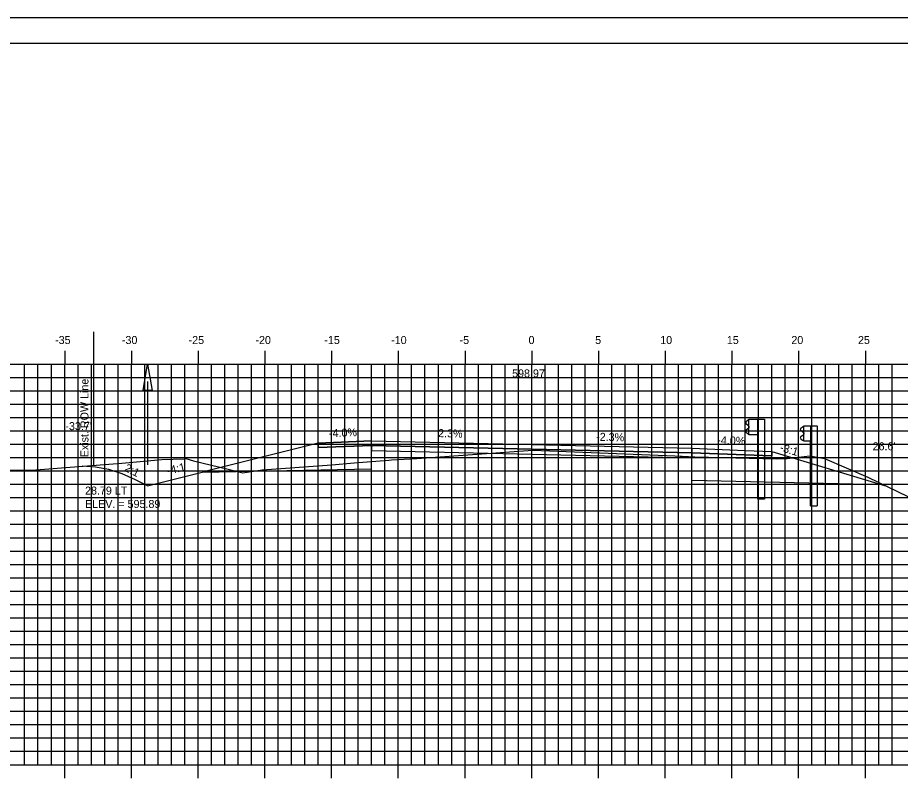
# Model space of a CAD drawing. Extents: x 1073864 to 1074034, y 779716 to 779826.
# Drawn here: x 1073908.9 to 1073975.1, y 779768.5 to 779825.6 of the extents above; entities that cross this region are included whole.
import ezdxf

# ---------------------------------------------------------------- set-up
doc = ezdxf.new("R2010")
doc.units = 0
for name, color, linetype in [('ANNOTATION', 7, 'Continuous'), ('BORDER', 7, 'Continuous'), ('D_Drainage_Ditch_Line', 7, 'Continuous'), ('D_Guardrail_Beam_Rt', 7, 'Continuous'), ('D_Roadway_Centerline', 7, 'Continuous'), ('D_Roadway_Centerline_Text', 7, 'Continuous'), ('D_Roadway_Edge_Pavement', 7, 'Continuous'), ('D_Roadway_Edge_Shoulder', 7, 'Continuous'), ('D_Roadway_Pavement', 7, 'Continuous'), ('D_Roadway_SlopeLines', 7, 'Continuous'), ('D_Roadway_SubGrade', 7, 'Continuous'), ('D_Text_Standard', 7, 'Continuous'), ('E_ROW_Line', 7, 'Continuous'), ('H_V ANNOTATION', 7, 'Continuous'), ('M_Guardrail', 7, 'Continuous'), ('MAJOR', 7, 'Continuous'), ('MINOR', 7, 'Continuous'), ('PLOT BOUNDARY', 7, 'Continuous'), ('S_Guardrail_Beam', 7, 'Continuous'), ('S_Roadway_Centerline', 7, 'Continuous')]:
    doc.layers.add(name, color=color, linetype=linetype)

msp = doc.modelspace()

# ---------------------------------------------------------------- linework, layer by layer
at = {"layer": 'BORDER'}
msp.add_lwpolyline([(1073872.472, 779718.706), (1074032.472, 779718.706), (1074032.472, 779823.706), (1073872.472, 779823.706)], close=True, dxfattribs=at)
at = {"layer": 'D_Drainage_Ditch_Line'}
msp.add_line((1073918.687, 779798.393), (1073918.687, 779792.15), dxfattribs=at)
msp.add_lwpolyline([(1073919.015, 779797.737), (1073918.359, 779797.737), (1073918.687, 779799.706)], close=True, dxfattribs=at)
at = {"layer": 'D_Guardrail_Beam_Rt'}
msp.add_lwpolyline([(1073963.751, 779795.512), (1073963.669, 779795.498), (1073963.652, 779795.491), (1073963.509, 779795.39), (1073963.509, 779795.247), (1073963.704, 779795.111), (1073963.738, 779795.046), (1073963.738, 779794.955), (1073963.704, 779794.89), (1073963.509, 779794.754), (1073963.509, 779794.611), (1073963.652, 779794.51), (1073963.669, 779794.504), (1073963.751, 779794.489)], dxfattribs=at)
for points in [[(1073963.751, 779795.591), (1073964.417, 779795.591), (1073964.417, 779794.41), (1073963.751, 779794.41)], [(1073964.417, 779795.591), (1073964.91, 779795.591), (1073964.91, 779789.587), (1073964.417, 779789.587)]]:
    msp.add_lwpolyline(points, close=True, dxfattribs=at)
at = {"layer": 'D_Roadway_Centerline'}
for points in [[(1073931.472, 779793.792), (1073935.472, 779793.952), (1073947.472, 779793.676), (1073959.472, 779793.4), (1073963.472, 779793.24), (1073965.472, 779793.16)], [(1073918.687, 779790.596), (1073922.762, 779791.614)], [(1073973.738, 779790.655), (1073974.082, 779790.551)]]:
    msp.add_lwpolyline(points, dxfattribs=at)
at = {"layer": 'D_Roadway_Edge_Pavement'}
msp.add_lwpolyline([(1073935.472, 779793.619), (1073935.472, 779793.952), (1073947.472, 779793.676), (1073959.472, 779793.4), (1073959.472, 779793.067), (1073947.472, 779793.343)], close=True, dxfattribs=at)
at = {"layer": 'D_Roadway_Edge_Shoulder'}
msp.add_lwpolyline([(1073935.472, 779793.952), (1073931.472, 779793.792), (1073931.472, 779793.459), (1073935.472, 779793.619)], close=True, dxfattribs=at)
msp.add_lwpolyline([(1073959.472, 779793.4), (1073963.472, 779793.24), (1073965.472, 779793.16), (1073965.472, 779792.827), (1073959.472, 779793.067), (1073959.472, 779793.4)], dxfattribs=at)
at = {"layer": 'D_Roadway_Pavement'}
msp.add_lwpolyline([(1073935.472, 779793.202), (1073935.472, 779793.619), (1073947.472, 779793.343), (1073959.472, 779793.067), (1073959.472, 779792.65), (1073947.472, 779792.926)], close=True, dxfattribs=at)
msp.add_lwpolyline([(1073935.472, 779793.619), (1073935.472, 779793.202)], dxfattribs=at)
at = {"layer": 'D_Roadway_SlopeLines'}
for points in [[(1073935.472, 779793.952), (1073931.472, 779793.792)], [(1073918.687, 779790.596), (1073917.78, 779791.049), (1073916.78, 779791.488), (1073915.78, 779791.802), (1073914.78, 779791.993), (1073913.78, 779792.059)]]:
    msp.add_lwpolyline(points, dxfattribs=at)
at = {"layer": 'D_Roadway_SubGrade'}
for points in [[(1073935.472, 779793.619), (1073931.472, 779793.459), (1073931.472, 779793.792), (1073922.762, 779791.614), (1073935.472, 779791.869), (1073935.472, 779793.619)], [(1073959.472, 779790.983), (1073959.472, 779791.567), (1073959.472, 779793.067), (1073959.472, 779793.067), (1073965.472, 779792.827), (1073965.472, 779793.16), (1073973.738, 779790.655)]]:
    msp.add_lwpolyline(points, close=True, dxfattribs=at)
at = {"layer": 'E_ROW_Line'}
msp.add_line((1073914.653, 779792.126), (1073914.653, 779802.126), dxfattribs=at)
msp.add_line((1073914.653, 779792.126), (1073914.653, 779802.126), dxfattribs=at)
at = {"layer": 'M_Guardrail'}
for p, q in [((1073968.359, 779795.087), (1073968.85, 779795.087)), ((1073968.85, 779795.087), (1073968.85, 779789.087)), ((1073968.359, 779789.087), (1073968.359, 779793.921)), ((1073968.359, 779789.087), (1073968.85, 779789.087))]:
    msp.add_line(p, q, dxfattribs=at)
at = {"layer": 'MAJOR'}
for p, q in [((1073912.472, 779800.708), (1073912.472, 779799.706)), ((1073917.472, 779800.708), (1073917.472, 779799.706)), ((1073922.472, 779800.708), (1073922.472, 779799.706)), ((1073927.472, 779800.708), (1073927.472, 779799.706)), ((1073932.472, 779800.708), (1073932.472, 779799.706)), ((1073937.472, 779800.708), (1073937.472, 779799.706)), ((1073942.472, 779800.708), (1073942.472, 779799.706)), ((1073947.472, 779800.708), (1073947.472, 779799.706)), ((1073952.472, 779800.708), (1073952.472, 779799.706)), ((1073957.472, 779800.708), (1073957.472, 779799.706)), ((1073962.472, 779800.708), (1073962.472, 779799.706)), ((1073967.472, 779800.708), (1073967.472, 779799.706)), ((1073972.472, 779800.708), (1073972.472, 779799.706)), ((1073877.472, 779799.706), (1074017.472, 779799.706)), ((1073877.472, 779799.706), (1074017.472, 779799.706)), ((1073912.472, 779769.706), (1073912.472, 779799.706)), ((1073917.472, 779769.706), (1073917.472, 779799.706)), ((1073922.472, 779769.706), (1073922.472, 779799.706)), ((1073927.472, 779769.706), (1073927.472, 779799.706)), ((1073932.472, 779769.706), (1073932.472, 779799.706)), ((1073937.472, 779769.706), (1073937.472, 779799.706)), ((1073942.472, 779769.706), (1073942.472, 779799.706)), ((1073947.472, 779769.706), (1073947.472, 779799.706)), ((1073952.472, 779769.706), (1073952.472, 779799.706)), ((1073957.472, 779769.706), (1073957.472, 779799.706)), ((1073962.472, 779769.706), (1073962.472, 779799.706)), ((1073967.472, 779769.706), (1073967.472, 779799.706)), ((1073972.472, 779769.706), (1073972.472, 779799.706)), ((1073877.472, 779794.706), (1074017.472, 779794.706)), ((1073877.472, 779789.706), (1074017.472, 779789.706)), ((1073877.472, 779784.706), (1074017.472, 779784.706)), ((1073877.472, 779779.706), (1074017.472, 779779.706)), ((1073877.472, 779774.706), (1074017.472, 779774.706)), ((1073877.472, 779769.706), (1074017.472, 779769.706)), ((1073877.472, 779769.706), (1074017.472, 779769.706)), ((1073912.472, 779768.704), (1073912.472, 779769.706)), ((1073917.472, 779768.704), (1073917.472, 779769.706)), ((1073922.472, 779768.704), (1073922.472, 779769.706)), ((1073927.472, 779768.704), (1073927.472, 779769.706)), ((1073932.472, 779768.704), (1073932.472, 779769.706)), ((1073937.472, 779768.704), (1073937.472, 779769.706)), ((1073942.472, 779768.704), (1073942.472, 779769.706)), ((1073947.472, 779768.704), (1073947.472, 779769.706)), ((1073952.472, 779768.704), (1073952.472, 779769.706)), ((1073957.472, 779768.704), (1073957.472, 779769.706)), ((1073962.472, 779768.704), (1073962.472, 779769.706)), ((1073967.472, 779768.704), (1073967.472, 779769.706)), ((1073972.472, 779768.704), (1073972.472, 779769.706))]:
    msp.add_line(p, q, dxfattribs=at)
at = {"layer": 'MINOR'}
for p, q in [((1073909.472, 779769.706), (1073909.472, 779799.706)), ((1073910.472, 779769.706), (1073910.472, 779799.706)), ((1073911.472, 779769.706), (1073911.472, 779799.706)), ((1073913.472, 779769.706), (1073913.472, 779799.706)), ((1073914.472, 779769.706), (1073914.472, 779799.706)), ((1073915.472, 779769.706), (1073915.472, 779799.706)), ((1073916.472, 779769.706), (1073916.472, 779799.706)), ((1073918.472, 779769.706), (1073918.472, 779799.706)), ((1073919.472, 779769.706), (1073919.472, 779799.706)), ((1073920.472, 779769.706), (1073920.472, 779799.706)), ((1073921.472, 779769.706), (1073921.472, 779799.706)), ((1073923.472, 779769.706), (1073923.472, 779799.706)), ((1073924.472, 779769.706), (1073924.472, 779799.706)), ((1073925.472, 779769.706), (1073925.472, 779799.706)), ((1073926.472, 779769.706), (1073926.472, 779799.706)), ((1073928.472, 779769.706), (1073928.472, 779799.706)), ((1073929.472, 779769.706), (1073929.472, 779799.706)), ((1073930.472, 779769.706), (1073930.472, 779799.706)), ((1073931.472, 779769.706), (1073931.472, 779799.706)), ((1073933.472, 779769.706), (1073933.472, 779799.706)), ((1073934.472, 779769.706), (1073934.472, 779799.706)), ((1073935.472, 779769.706), (1073935.472, 779799.706)), ((1073936.472, 779769.706), (1073936.472, 779799.706)), ((1073938.472, 779769.706), (1073938.472, 779799.706)), ((1073939.472, 779769.706), (1073939.472, 779799.706)), ((1073940.472, 779769.706), (1073940.472, 779799.706)), ((1073941.472, 779769.706), (1073941.472, 779799.706)), ((1073943.472, 779769.706), (1073943.472, 779799.706)), ((1073944.472, 779769.706), (1073944.472, 779799.706)), ((1073945.472, 779769.706), (1073945.472, 779799.706)), ((1073946.472, 779769.706), (1073946.472, 779799.706)), ((1073948.472, 779769.706), (1073948.472, 779799.706)), ((1073949.472, 779769.706), (1073949.472, 779799.706)), ((1073950.472, 779769.706), (1073950.472, 779799.706)), ((1073951.472, 779769.706), (1073951.472, 779799.706)), ((1073953.472, 779769.706), (1073953.472, 779799.706)), ((1073954.472, 779769.706), (1073954.472, 779799.706)), ((1073955.472, 779769.706), (1073955.472, 779799.706)), ((1073956.472, 779769.706), (1073956.472, 779799.706)), ((1073958.472, 779769.706), (1073958.472, 779799.706)), ((1073959.472, 779769.706), (1073959.472, 779799.706)), ((1073960.472, 779769.706), (1073960.472, 779799.706)), ((1073961.472, 779769.706), (1073961.472, 779799.706)), ((1073963.472, 779769.706), (1073963.472, 779799.706)), ((1073964.472, 779769.706), (1073964.472, 779799.706)), ((1073965.472, 779769.706), (1073965.472, 779799.706)), ((1073966.472, 779769.706), (1073966.472, 779799.706)), ((1073968.472, 779769.706), (1073968.472, 779799.706)), ((1073969.472, 779769.706), (1073969.472, 779799.706)), ((1073970.472, 779769.706), (1073970.472, 779799.706)), ((1073971.472, 779769.706), (1073971.472, 779799.706)), ((1073973.472, 779769.706), (1073973.472, 779799.706)), ((1073974.472, 779769.706), (1073974.472, 779799.706)), ((1073877.472, 779798.706), (1074017.472, 779798.706)), ((1073877.472, 779797.706), (1074017.472, 779797.706)), ((1073877.472, 779796.706), (1074017.472, 779796.706)), ((1073877.472, 779795.706), (1074017.472, 779795.706)), ((1073877.472, 779793.706), (1074017.472, 779793.706)), ((1073877.472, 779792.706), (1074017.472, 779792.706)), ((1073877.472, 779791.706), (1074017.472, 779791.706)), ((1073877.472, 779790.706), (1074017.472, 779790.706)), ((1073877.472, 779788.706), (1074017.472, 779788.706)), ((1073877.472, 779787.706), (1074017.472, 779787.706)), ((1073877.472, 779786.706), (1074017.472, 779786.706)), ((1073877.472, 779785.706), (1074017.472, 779785.706)), ((1073877.472, 779783.706), (1074017.472, 779783.706)), ((1073877.472, 779782.706), (1074017.472, 779782.706)), ((1073877.472, 779781.706), (1074017.472, 779781.706)), ((1073877.472, 779780.706), (1074017.472, 779780.706)), ((1073877.472, 779778.706), (1074017.472, 779778.706)), ((1073877.472, 779777.706), (1074017.472, 779777.706)), ((1073877.472, 779776.706), (1074017.472, 779776.706)), ((1073877.472, 779775.706), (1074017.472, 779775.706)), ((1073877.472, 779773.706), (1074017.472, 779773.706)), ((1073877.472, 779772.706), (1074017.472, 779772.706)), ((1073877.472, 779771.706), (1074017.472, 779771.706)), ((1073877.472, 779770.706), (1074017.472, 779770.706))]:
    msp.add_line(p, q, dxfattribs=at)
at = {"layer": 'PLOT BOUNDARY'}
msp.add_lwpolyline([(1073864.379, 779715.646), (1074034.379, 779715.646), (1074034.379, 779825.646), (1073864.379, 779825.646)], close=True, dxfattribs=at)
at = {"layer": 'S_Guardrail_Beam'}
for p, q in [((1073967.771, 779794.993), (1073967.627, 779794.893)), ((1073967.627, 779794.75), (1073967.822, 779794.614)), ((1073967.869, 779795.014), (1073967.787, 779795)), ((1073967.869, 779795.087), (1073968.359, 779795.087)), ((1073967.869, 779793.921), (1073967.869, 779795.087)), ((1073968.359, 779795.087), (1073968.359, 779793.921)), ((1073967.822, 779794.394), (1073967.627, 779794.258)), ((1073967.627, 779794.115), (1073967.771, 779794.015)), ((1073967.856, 779794.549), (1073967.856, 779794.458)), ((1073967.787, 779794.008), (1073967.869, 779793.994)), ((1073968.359, 779793.921), (1073967.869, 779793.921))]:
    msp.add_line(p, q, dxfattribs=at)
for centre, major_axis, start_param, end_param in [((1073967.677, 779794.822), (-0.0877, 0), 5.323254, 7.243116), ((1073967.794, 779794.959), (-0.0417, 0), 4.886922, 5.323254), ((1073967.677, 779794.186), (-0.0877, 0), 5.323254, 7.243116), ((1073967.777, 779794.549), (0.0789, 0), 0, 0.959931), ((1073967.777, 779794.458), (0.0789, 0), 5.323254, 6.283185), ((1073967.794, 779794.049), (-0.0417, 0), 0.959931, 1.396263)]:
    msp.add_ellipse(centre, major_axis=major_axis, ratio=0.995501, start_param=start_param, end_param=end_param, dxfattribs=at)
at = {"layer": 'S_Roadway_Centerline'}
msp.add_lwpolyline([(1073902.537, 779791.834), (1073909.973, 779791.769), (1073916.76, 779792.287), (1073919.755, 779792.56), (1073921.429, 779792.601), (1073921.561, 779792.636), (1073922.121, 779792.469), (1073924.728, 779791.838), (1073925.809, 779791.552), (1073927.259, 779791.791), (1073932.485, 779792.17), (1073934.153, 779792.308), (1073936.763, 779792.521), (1073936.961, 779792.527), (1073938.866, 779792.645), (1073947.56, 779793.265), (1073958.185, 779792.833), (1073958.587, 779792.816), (1073958.753, 779792.814), (1073959.699, 779792.771), (1073965.8, 779792.617), (1073966.617, 779792.645), (1073968.308, 779792.826), (1073969.409, 779792.64), (1073972.663, 779791.235), (1073982.275, 779786.599)], dxfattribs=at)

# ---------------------------------------------------------------- texts
at = {"layer": 'ANNOTATION'}
for s, rotation, p in [('-4.0%', 2.29061, (1073932.288, 779794.225)), ('2.3%', 358.68243, (1073940.452, 779794.238)), ('-2.3%', 358.68243, (1073952.292, 779793.965)), ('-4.0%', 357.70939, (1073961.368, 779793.725)), ('-3:1', 343.1416, (1073966.014, 779793.217)), ('2:1', 333.43495, (1073916.9, 779791.738)), ('-4:1', 14.03624, (1073920.219, 779791.41))]:
    msp.add_text(s, height=0.6, rotation=rotation, dxfattribs=at).set_placement(p)
for s, p in [('28.79 LT', (1073913.998, 779789.932)), ('ELEV. = 595.89', (1073913.998, 779788.93))]:
    msp.add_text(s, height=0.6, dxfattribs=at).set_placement(p)
at = {"layer": 'D_Roadway_Centerline_Text'}
msp.add_text('598.97', height=0.6, dxfattribs=at).set_placement((1073946.001, 779798.708))
at = {"layer": 'D_Text_Standard'}
for s, p in [("-33.7'", (1073912.525, 779794.759)), ("26.6'", (1073973.014, 779793.251))]:
    msp.add_text(s, height=0.6, dxfattribs=at).set_placement(p)
at = {"layer": 'E_ROW_Line'}
msp.add_text('Exist. ROW Line', height=0.6, rotation=90, dxfattribs=at).set_placement((1073914.253, 779792.726))
at = {"layer": 'H_V ANNOTATION'}
for s, p in [('-35', (1073911.752, 779801.206)), ('-30', (1073916.76, 779801.206)), ('-25', (1073921.758, 779801.206)), ('-20', (1073926.766, 779801.206)), ('-15', (1073931.929, 779801.206)), ('-10', (1073936.937, 779801.206)), ('-5', (1073942.063, 779801.206)), ('0', (1073947.231, 779801.206)), ('5', (1073952.223, 779801.206)), ('10', (1073957.098, 779801.206)), ('15', (1073962.09, 779801.206)), ('20', (1073966.926, 779801.206)), ('25', (1073971.918, 779801.206))]:
    msp.add_text(s, height=0.6, dxfattribs=at).set_placement(p)

doc.saveas('drawing.dxf')
